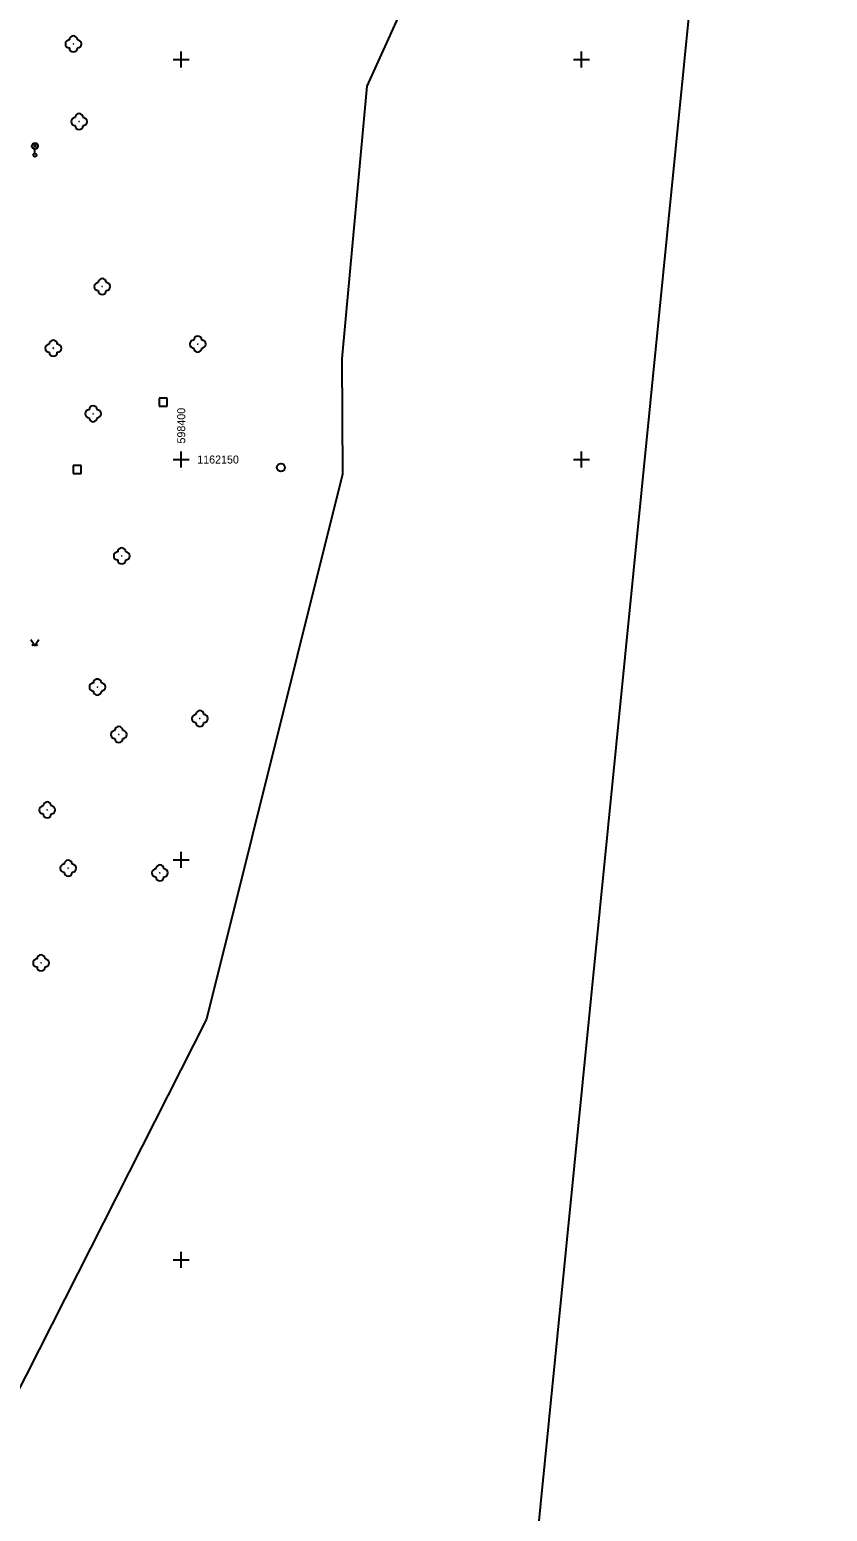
# Model space of a CAD drawing. Extents: x -598693 to -598360, y -1162453 to -1162007.
# Drawn here: x -598409.5 to -598359.6, y -1162215.7 to -1162123.1 of the extents above; entities that cross this region are included whole.
import ezdxf

# ---------------------------------------------------------------- set-up
doc = ezdxf.new("R2010")
doc.units = 0
for name, color, linetype in [('Vrstva 10', 7, 'Continuous'), ('Vrstva 14', 7, 'Continuous'), ('Vrstva 2', 7, 'Continuous'), ('Vrstva 23', 7, 'Continuous'), ('Vrstva 25', 7, 'Continuous'), ('Vrstva 29', 7, 'Continuous'), ('Vrstva 62', 7, 'Continuous')]:
    doc.layers.add(name, color=color, linetype=linetype)

msp = doc.modelspace()

# ---------------------------------------------------------------- linework, layer by layer
at = {"layer": 'Vrstva 10'}
msp.add_lwpolyline([(-598377.96, -1162111.55), (-598380.34, -1162110.85), (-598382.6, -1162113.85), (-598388.4, -1162126.67), (-598389.97, -1162143.7), (-598389.93, -1162150.91), (-598398.41, -1162184.97), (-598409.68, -1162207.21), (-598446.29, -1162278.33)], dxfattribs=at)
at = {"layer": 'Vrstva 14'}
msp.add_lwpolyline([(-598409.39, -1162161.235), (-598409.14, -1162161.61), (-598408.89, -1162161.235)], dxfattribs=at)
for centre, radius in [((-598406.74, -1162124.03), 0.00025), ((-598406.38, -1162128.89), 0.00025), ((-598404.93, -1162139.19), 0.00025), ((-598407.99, -1162143.05), 0.00025), ((-598398.97, -1162142.79), 0.00025), ((-598405.51, -1162147.14), 0.00025), ((-598403.72, -1162156.02), 0.00025), ((-598409.265, -1162161.585), 0.025), ((-598409.015, -1162161.585), 0.025), ((-598405.24, -1162164.21), 0.00025), ((-598398.83, -1162166.18), 0.00025), ((-598403.9, -1162167.18), 0.00025), ((-598408.37, -1162171.89), 0.00025), ((-598407.06, -1162175.53), 0.00025), ((-598401.33, -1162175.82), 0.00025), ((-598408.76, -1162181.45), 0.00025)]:
    msp.add_circle(centre, radius, dxfattribs=at)
for centre, start, end in [((-598406.99, -1162124.03), 89.99999, 269.99999), ((-598406.74, -1162123.78), 0, 179.99999), ((-598406.49, -1162124.03), 270, 89.99999), ((-598406.74, -1162124.28), 179.99999, 359.99999), ((-598406.38, -1162128.64), 0, 179.99999), ((-598406.63, -1162128.89), 89.99999, 269.99999), ((-598406.38, -1162129.14), 179.99999, 359.99999), ((-598406.13, -1162128.89), 270, 89.99999), ((-598405.18, -1162139.19), 89.99999, 269.99999), ((-598404.93, -1162138.94), 0, 179.99999), ((-598404.93, -1162139.44), 179.99999, 359.99999), ((-598404.68, -1162139.19), 270, 89.99999), ((-598398.97, -1162142.54), 0, 179.99999), ((-598408.24, -1162143.05), 89.99999, 269.99999), ((-598407.99, -1162142.8), 0, 179.99999), ((-598407.74, -1162143.05), 270, 89.99999), ((-598399.22, -1162142.79), 89.99999, 269.99999), ((-598398.97, -1162143.04), 179.99999, 359.99999), ((-598398.72, -1162142.79), 270, 89.99999), ((-598407.99, -1162143.3), 179.99999, 359.99999), ((-598405.76, -1162147.14), 89.99999, 269.99999), ((-598405.51, -1162146.89), 0, 179.99999), ((-598405.26, -1162147.14), 270, 89.99999), ((-598405.51, -1162147.39), 179.99999, 359.99999), ((-598403.97, -1162156.02), 89.99999, 269.99999), ((-598403.72, -1162155.77), 0, 179.99999), ((-598403.47, -1162156.02), 270, 89.99999), ((-598403.72, -1162156.27), 179.99999, 359.99999), ((-598405.49, -1162164.21), 89.99999, 269.99999), ((-598405.24, -1162163.96), 0, 179.99999), ((-598405.24, -1162164.46), 179.99999, 359.99999), ((-598404.99, -1162164.21), 270, 89.99999), ((-598399.08, -1162166.18), 89.99999, 269.99999), ((-598398.83, -1162165.93), 0, 179.99999), ((-598398.58, -1162166.18), 270, 89.99999), ((-598404.15, -1162167.18), 89.99999, 269.99999), ((-598403.9, -1162166.93), 0, 179.99999), ((-598403.65, -1162167.18), 270, 89.99999), ((-598398.83, -1162166.43), 179.99999, 359.99999), ((-598403.9, -1162167.43), 179.99999, 359.99999), ((-598408.62, -1162171.89), 89.99999, 269.99999), ((-598408.37, -1162171.64), 0, 179.99999), ((-598408.12, -1162171.89), 270, 89.99999), ((-598408.37, -1162172.14), 179.99999, 359.99999), ((-598407.31, -1162175.53), 89.99999, 269.99999), ((-598407.06, -1162175.28), 0, 179.99999), ((-598406.81, -1162175.53), 270, 89.99999), ((-598401.58, -1162175.82), 89.99999, 269.99999), ((-598401.33, -1162175.57), 0, 179.99999), ((-598401.08, -1162175.82), 270, 89.99999), ((-598407.06, -1162175.78), 179.99999, 359.99999), ((-598401.33, -1162176.07), 179.99999, 359.99999), ((-598409.01, -1162181.45), 89.99999, 269.99999), ((-598408.76, -1162181.2), 0, 179.99999), ((-598408.51, -1162181.45), 270, 89.99999), ((-598408.76, -1162181.7), 179.99999, 359.99999)]:
    msp.add_arc(centre, 0.25, start, end, dxfattribs=at)
at = {"layer": 'Vrstva 2'}
msp.add_lwpolyline([(-598507.399, -1162020.712), (-598549.031, -1162438.644), (-598401.263, -1162453.364), (-598359.63, -1162035.432)], close=True, dxfattribs=at)
at = {"layer": 'Vrstva 23'}
for p, q in [((-598400.87, -1162146.17), (-598401.37, -1162146.17)), ((-598401.37, -1162146.17), (-598401.37, -1162146.67)), ((-598401.37, -1162146.67), (-598400.87, -1162146.67)), ((-598400.87, -1162146.67), (-598400.87, -1162146.17)), ((-598406.25, -1162150.38), (-598406.75, -1162150.38)), ((-598406.75, -1162150.38), (-598406.75, -1162150.88)), ((-598406.25, -1162150.88), (-598406.25, -1162150.38)), ((-598406.75, -1162150.88), (-598406.25, -1162150.88))]:
    msp.add_line(p, q, dxfattribs=at)
at = {"layer": 'Vrstva 25'}
msp.add_circle((-598393.77, -1162150.5), 0.25, dxfattribs=at)
at = {"layer": 'Vrstva 29'}
for p, q in [((-598409.272, -1162130.549), (-598409.008, -1162130.285)), ((-598409.004, -1162130.548), (-598409.268, -1162130.283)), ((-598409.14, -1162130.88), (-598409.14, -1162130.605))]:
    msp.add_line(p, q, dxfattribs=at)
for centre, radius in [((-598409.14, -1162130.417), 0.188), ((-598409.14, -1162130.98), 0.1)]:
    msp.add_circle(centre, radius, dxfattribs=at)
at = {"layer": 'Vrstva 62'}
for p, q in [((-598400, -1162125.5), (-598400, -1162124.5)), ((-598375, -1162125.5), (-598375, -1162124.5)), ((-598400.5, -1162125), (-598399.5, -1162125)), ((-598375.5, -1162125), (-598374.5, -1162125)), ((-598400, -1162150.5), (-598400, -1162149.5)), ((-598375, -1162150.5), (-598375, -1162149.5)), ((-598400.5, -1162150), (-598399.5, -1162150)), ((-598375.5, -1162150), (-598374.5, -1162150)), ((-598400, -1162175.5), (-598400, -1162174.5)), ((-598400.5, -1162175), (-598399.5, -1162175)), ((-598400, -1162200.5), (-598400, -1162199.5)), ((-598400.5, -1162200), (-598399.5, -1162200))]:
    msp.add_line(p, q, dxfattribs=at)

# ---------------------------------------------------------------- texts
msp.add_text('598400', height=0.5, rotation=90, dxfattribs=at).set_placement((-598399.75, -1162149))
msp.add_text('1162150', height=0.5, dxfattribs=at).set_placement((-598399, -1162150.25))

doc.saveas('drawing.dxf')
